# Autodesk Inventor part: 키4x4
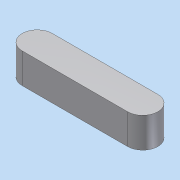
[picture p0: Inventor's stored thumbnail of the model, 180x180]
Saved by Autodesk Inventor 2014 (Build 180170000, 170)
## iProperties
Company: 한국ATC센터
Created: 2011-07
Part Number: 키4x4
Document SubType Name: Modeling
Designer: KYOUNG IL JANG
Density: 7.86 g/cm^3
Mass: 2.15573 g
Surface Area: 2.99398 cm^2
Volume: 0.274265 cm^3
Vendor: CBT Solutions
Material: 강, 연강
Appearance: 강철
Author: KYOUNG IL JANG
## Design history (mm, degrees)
sketch "스케치1"
  geometry: L1 (0, 2)-(14, 2); L2 (0, -2)-(14, -2); A1 r 2 centre (0, 0) between (0, 2) and (0, -2); A2 r 2 centre (14, 0) between (14, -2) and (14, 2); 1 further point
  constraints: 4 end point, 4 point on circle, 3 tangent, 2 centre point, 1 coincident, 1 equal radius, 1 horizontal alignment, 1 parallel
  dimensions: "d0" = 4 distance between parallel lines of L2 L1; "d1" = 18 dimension on A2 A1
extrude "돌출1" new body sketch "스케치1" distance "d2" = 4; taper "d3" = 0 deg
node "솔리드1"
